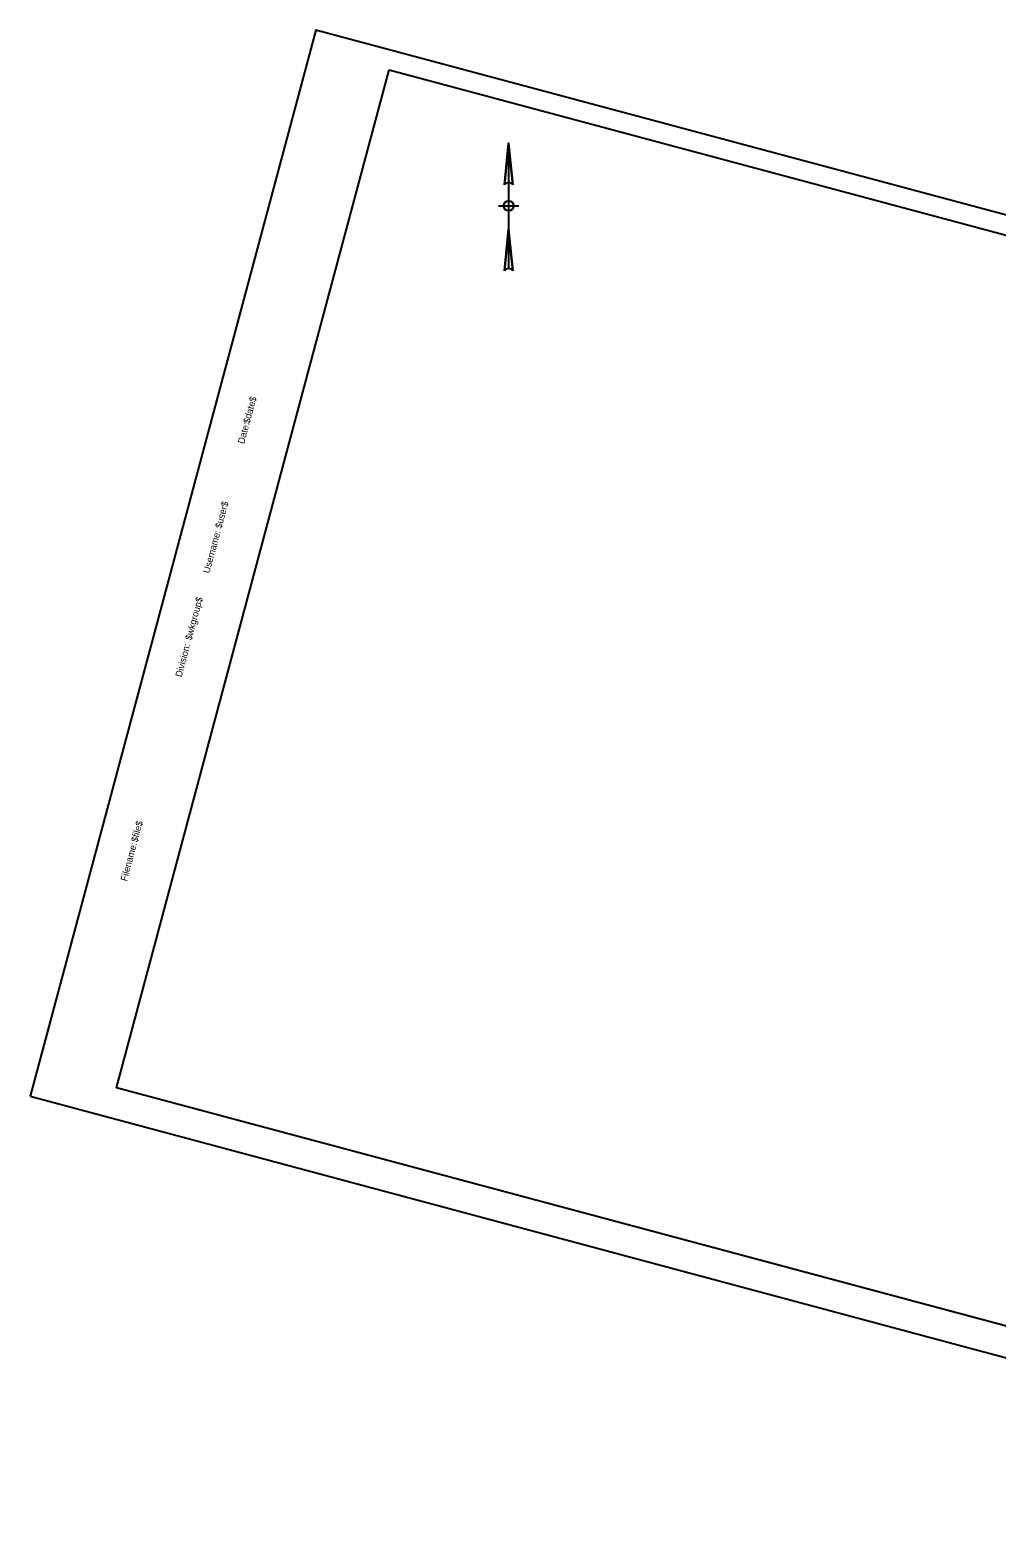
# Model space of a CAD drawing. Extents: x 1762439 to 1763402, y 480738 to 481489.
# Drawn here: x 1762439 to 1762920, y 480738 to 481489 of the extents above; entities that cross this region are included whole.
import ezdxf

# ---------------------------------------------------------------- set-up
doc = ezdxf.new("R2010")
doc.units = 0
for name, color, linetype in [('BORDER', 7, 'Continuous'), ('CLIPS', 7, 'Continuous'), ('H_V CONTROLS', 7, 'Continuous'), ('PLOT BOUNDARY', 7, 'Continuous')]:
    doc.layers.add(name, color=color, linetype=linetype)

msp = doc.modelspace()

# ---------------------------------------------------------------- linework, layer by layer
at = {"layer": 'BORDER'}
msp.add_lwpolyline([(1762617.53, 481469.16), (1763390.27, 481262.1), (1763254.39, 480754.99), (1762481.65, 480962.05)], close=True, dxfattribs=at)
at = {"layer": 'CLIPS'}
msp.add_lwpolyline([(1762617.53, 481469.16), (1763341.98, 481275.04), (1763206.1, 480767.93), (1762481.65, 480962.05)], close=True, dxfattribs=at)
at = {"layer": 'H_V CONTROLS'}
for p, q in [((1762674.95, 481411.87), (1762677.04, 481432.7)), ((1762677.04, 481432.7), (1762677.04, 481370.2)), ((1762677.04, 481432.7), (1762679.12, 481411.87)), ((1762672.04, 481401.45), (1762682.04, 481401.45)), ((1762674.95, 481369.08), (1762677.04, 481389.92)), ((1762677.04, 481389.92), (1762679.12, 481369.08))]:
    msp.add_line(p, q, dxfattribs=at)
for points in [[(1762679.12, 481411.87), (1762677.04, 481432.7), (1762675.99, 481422.28), (1762674.95, 481411.87)], [(1762679.12, 481369.08), (1762677.04, 481389.92), (1762675.99, 481379.5), (1762674.95, 481369.08)]]:
    msp.add_lwpolyline(points, dxfattribs=at)
msp.add_circle((1762677.04, 481401.45), 2.5, dxfattribs=at)
for centre in [(1762677.04, 481410.48), (1762677.04, 481410.48), (1762677.04, 481367.7), (1762677.04, 481367.7)]:
    msp.add_arc(centre, 2.5, 33.55731, 146.44269, dxfattribs=at)
at = {"layer": 'PLOT BOUNDARY'}
msp.add_lwpolyline([(1762438.61, 480957.75), (1763259.64, 480737.75), (1763401.99, 481269.01), (1762580.96, 481489)], close=True, dxfattribs=at)

# ---------------------------------------------------------------- texts
at = {"layer": 'BORDER'}
for s, p in [('$date$', (1762547.91, 481292.69)), ('Date:', (1762545.21, 481282.6)), ('$user$', (1762533.92, 481240.46)), ('Username:', (1762527.93, 481218.13)), ('$wkgroup$', (1762519.01, 481184.82)), ('Division:', (1762514.09, 481166.45)), ('$file$', (1762492.03, 481084.15)), ('Filename:', (1762486.82, 481064.7))]:
    msp.add_text(s, height=3.348, rotation=75, dxfattribs=at).set_placement(p)

doc.saveas('drawing.dxf')
